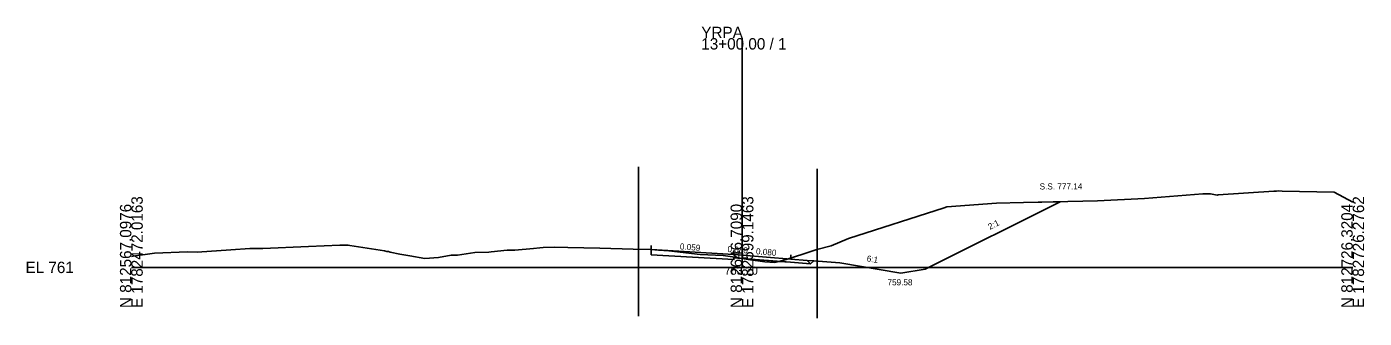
# Model space of a CAD drawing. Extents: x -26 to 2603, y -14 to 9545.
# Drawn here: x -25.7 to 302.8, y 2987.5 to 3059.1 of the extents above; entities that cross this region are included whole.
import ezdxf

# ---------------------------------------------------------------- set-up
doc = ezdxf.new("R2010")
doc.units = 0
for name, color, linetype in [('Exist Cross Section Cell', 7, 'Continuous'), ('Exist XS Center Line Elevation Label', 7, 'Continuous'), ('Exist XS Ground Line', 7, 'Continuous'), ('Prop XS Ditch Slope Text', 7, 'Continuous'), ('Prop XS Ditch Standard Text', 7, 'Continuous'), ('Prop XS Dump Level', 7, 'Continuous'), ('Prop XS Earthwork Shape', 7, 'Continuous'), ('Prop XS EOT Tick Mark', 7, 'Continuous'), ('Prop XS Exc Vertical Line 2', 7, 'Continuous'), ('Prop XS Finish Grade', 7, 'Continuous'), ('Prop XS Finish Grade Earthwork', 7, 'Continuous'), ('Prop XS Finish Grade Paved Shoulder', 7, 'Continuous'), ('Prop XS Finish Grade Pavement', 7, 'Continuous'), ('Prop XS Pvmt Edge Slope', 7, 'Continuous'), ('Prop XS SE Text', 7, 'Continuous'), ('Prop XS Side Slope Text', 7, 'Continuous'), ('Prop XS SS Elevation Text', 7, 'Continuous'), ('Prop XS Subgrade Earthwork', 7, 'Continuous'), ('Scratch_Level_6', 7, 'Continuous')]:
    doc.layers.add(name, color=color, linetype=linetype)

msp = doc.modelspace()

# ---------------------------------------------------------------- linework, layer by layer
at = {"layer": 'Exist Cross Section Cell'}
for p, q in [((150, 3000), (150, 3056.32)), ((0, 3000), (150, 3000)), ((150, 3000), (300, 3000))]:
    msp.add_line(p, q, dxfattribs=at)
at = {"layer": 'Exist XS Ground Line'}
for p, q in [((212.53, 3015.8), (219.17, 3015.96)), ((219.17, 3015.96), (237.29, 3016.32)), ((237.29, 3016.32), (248.84, 3016.91)), ((248.84, 3016.91), (263.16, 3018.08)), ((263.16, 3018.08), (265.09, 3018.03)), ((265.09, 3018.03), (266.68, 3017.78)), ((266.68, 3017.78), (266.99, 3017.86)), ((266.99, 3017.86), (280.67, 3018.74)), ((280.67, 3018.74), (281.25, 3018.76)), ((281.25, 3018.76), (281.75, 3018.77)), ((281.75, 3018.77), (282.65, 3018.73)), ((282.65, 3018.73), (295.44, 3018.47)), ((295.44, 3018.47), (300, 3016.01)), ((176.14, 3007.12), (199.68, 3014.66)), ((199.68, 3014.66), (200.28, 3014.85)), ((200.28, 3014.85), (212.53, 3015.8)), ((171.87, 3005.33), (176.14, 3007.12)), ((0.45, 3002.74), (5.66, 3003.45)), ((5.66, 3003.45), (13.8, 3003.8)), ((13.8, 3003.8), (16.13, 3003.76)), ((16.13, 3003.76), (24.47, 3004.32)), ((24.47, 3004.32), (29.14, 3004.65)), ((29.14, 3004.65), (32.28, 3004.66)), ((32.28, 3004.66), (43.51, 3005.11)), ((43.51, 3005.11), (51.23, 3005.45)), ((51.23, 3005.45), (53.29, 3005.45)), ((53.29, 3005.45), (53.65, 3005.41)), ((53.65, 3005.41), (61.12, 3004.25)), ((61.12, 3004.25), (62.17, 3004.05)), ((62.17, 3004.05), (62.74, 3003.87)), ((62.74, 3003.87), (63.2, 3003.87)), ((63.2, 3003.87), (63.59, 3003.73)), ((63.59, 3003.73), (65.95, 3003.26)), ((65.95, 3003.26), (68.4, 3002.82)), ((68.4, 3002.82), (72.06, 3002.2)), ((75.46, 3002.41), (78.55, 3003.03)), ((78.55, 3003.03), (80.15, 3002.98)), ((80.15, 3002.98), (84.39, 3003.68)), ((84.39, 3003.68), (87.84, 3003.75)), ((87.84, 3003.75), (88.39, 3003.8)), ((88.39, 3003.8), (92.3, 3004.2)), ((92.3, 3004.2), (94.21, 3004.26)), ((94.21, 3004.26), (98.75, 3004.65)), ((98.75, 3004.65), (100.35, 3004.82)), ((100.35, 3004.82), (101.14, 3004.85)), ((101.14, 3004.85), (104, 3004.96)), ((104, 3004.96), (107.25, 3004.89)), ((107.25, 3004.89), (115.04, 3004.74)), ((115.04, 3004.74), (123.26, 3004.49)), ((123.26, 3004.49), (127.72, 3004.36)), ((127.72, 3004.36), (129.46, 3004.24)), ((129.46, 3004.24), (132.01, 3004.08)), ((132.01, 3004.08), (139.7, 3003.13)), ((139.7, 3003.13), (145.39, 3002.91)), ((145.39, 3002.91), (148.26, 3002.47)), ((160.84, 3001.93), (165.15, 3003.31)), ((165.15, 3003.31), (168.35, 3004.37)), ((168.35, 3004.37), (171.87, 3005.33)), ((0, 3002.71), (0.45, 3002.74)), ((72.06, 3002.2), (75.46, 3002.41)), ((148.26, 3002.47), (150, 3002.2)), ((150, 3002.2), (151.55, 3001.96)), ((151.55, 3001.96), (155.63, 3001.33)), ((155.63, 3001.33), (157.97, 3001.16)), ((157.97, 3001.16), (160.84, 3001.93))]:
    msp.add_line(p, q, dxfattribs=at)
at = {"layer": 'Prop XS Dump Level'}
for p, q in [((148, 3003.16), (150, 3003)), ((150, 3003), (162, 3002.04))]:
    msp.add_line(p, q, dxfattribs=at)
at = {"layer": 'Prop XS Earthwork Shape'}
for points in [[(189, 2998.58), (195, 2999.58), (228.12, 3016.14), (219.17, 3015.96), (212.53, 3015.8), (200.28, 3014.85), (199.68, 3014.66), (176.14, 3007.12), (171.87, 3005.33), (168.35, 3004.37), (165.15, 3003.31), (160.84, 3001.93), (159.12, 3001.47), (161.94, 3001.25), (166.86, 3000.85), (167.6, 3001.59), (174, 3001.08)], [(127.71, 3004.36), (127.72, 3004.36), (129.46, 3004.24), (132.01, 3004.08), (139.7, 3003.13), (145.39, 3002.91), (148.26, 3002.47), (149.92, 3002.21), (148, 3002.36), (148, 3001.91), (127.71, 3003.1)], [(149.94, 3002.21), (159.12, 3001.47), (157.97, 3001.16), (155.63, 3001.33), (151.55, 3001.96), (150, 3002.2), (149.92, 3002.21)]]:
    msp.add_lwpolyline(points, close=True, dxfattribs=at)
at = {"layer": 'Prop XS EOT Tick Mark'}
for p, q in [((127.71, 3004.36), (127.71, 3005.36)), ((148, 3003.16), (148, 3004.16)), ((162, 3002.04), (162, 3003.04))]:
    msp.add_line(p, q, dxfattribs=at)
at = {"layer": 'Prop XS Exc Vertical Line 2'}
for p, q in [((124.61, 2987.98), (124.61, 3024.66)), ((168.47, 2987.5), (168.47, 3024.18))]:
    msp.add_line(p, q, dxfattribs=at)
at = {"layer": 'Prop XS Finish Grade'}
msp.add_line((166, 3001.72), (167.6, 3001.59), dxfattribs=at)
at = {"layer": 'Prop XS Finish Grade Earthwork'}
for p, q in [((195, 2999.58), (228.12, 3016.14)), ((167.6, 3001.59), (174, 3001.08)), ((174, 3001.08), (189, 2998.58)), ((189, 2998.58), (195, 2999.58))]:
    msp.add_line(p, q, dxfattribs=at)
at = {"layer": 'Prop XS Finish Grade Paved Shoulder'}
for p, q in [((148, 3003.16), (127.71, 3004.36)), ((162, 3002.04), (166, 3001.72))]:
    msp.add_line(p, q, dxfattribs=at)
at = {"layer": 'Prop XS Finish Grade Pavement'}
for p, q in [((148, 3003.16), (150, 3003)), ((150, 3003), (162, 3002.04))]:
    msp.add_line(p, q, dxfattribs=at)
at = {"layer": 'Prop XS Pvmt Edge Slope'}
msp.add_line((166, 3001.72), (166.86, 3000.85), dxfattribs=at)
at = {"layer": 'Prop XS Subgrade Earthwork'}
for p, q in [((127.71, 3003.1), (127.71, 3004.36)), ((148, 3001.91), (127.71, 3003.1)), ((148, 3002.36), (149.94, 3002.21)), ((148, 3001.91), (148, 3002.36)), ((149.94, 3002.21), (161.94, 3001.25)), ((161.94, 3001.25), (166.86, 3000.85)), ((166.86, 3000.85), (167.6, 3001.59))]:
    msp.add_line(p, q, dxfattribs=at)
at = {"layer": 'Scratch_Level_6'}
for points in [[(148, 3001.91), (127.71, 3003.1), (127.71, 3004.36), (127.78, 3004.35), (129.46, 3004.24), (132.01, 3004.08), (139.7, 3003.13), (145.39, 3002.91), (148.26, 3002.47), (149.92, 3002.21), (148, 3002.36)], [(166, 3001.72), (167.6, 3001.59), (166.86, 3000.85), (161.94, 3001.25), (159.12, 3001.47), (160.84, 3001.93), (161.33, 3002.09), (162, 3002.04)]]:
    msp.add_lwpolyline(points, close=True, dxfattribs=at)

# ---------------------------------------------------------------- texts
at = {"layer": 'Exist Cross Section Cell'}
for s, p in [('YRPA', (140, 3056.32)), ('13+00.00 / 1', (140, 3053.52)), ('EL 761', (-26, 2998.6))]:
    msp.add_text(s, height=2.8, dxfattribs=at).set_placement(p)
for s, p in [('E 1782472.0163', (2.8, 2990)), ('E 1782599.1463', (152.8, 2990)), ('E 1782726.2762', (302.8, 2990)), ('N 812567.0976', (0, 2990)), ('N 812646.7090', (150, 2990)), ('N 812726.3204', (300, 2990))]:
    msp.add_text(s, height=2.8, rotation=90, dxfattribs=at).set_placement(p)
at = {"layer": 'Exist XS Center Line Elevation Label'}
msp.add_text('763.20', height=2, dxfattribs=at).set_placement((145.71, 2998.2))
at = {"layer": 'Prop XS Ditch Slope Text'}
msp.add_text('6:1', height=1.5, rotation=350.5377, dxfattribs=at).set_placement((180.55, 3001.51))
at = {"layer": 'Prop XS Ditch Standard Text'}
msp.add_text('759.58', height=1.5, dxfattribs=at).set_placement((185.74, 2995.58))
at = {"layer": 'Prop XS Dump Level'}
msp.add_text('Case4', height=0.04, dxfattribs=at).set_placement((174, 3001.04))
at = {"layer": 'Prop XS SE Text'}
for s, p in [('0.059', (134.69, 3004.43)), ('0.080', (146.38, 3003.79)), ('0.080', (153.38, 3003.23))]:
    msp.add_text(s, height=1.5, rotation=355.4261, dxfattribs=at).set_placement(p)
at = {"layer": 'Prop XS Side Slope Text'}
msp.add_text('2:1', height=1.5, rotation=26.5651, dxfattribs=at).set_placement((210.89, 3009.2))
at = {"layer": 'Prop XS SS Elevation Text'}
msp.add_text('S.S. 777.14', height=1.5, dxfattribs=at).set_placement((223.11, 3019.14))

doc.saveas('drawing.dxf')
